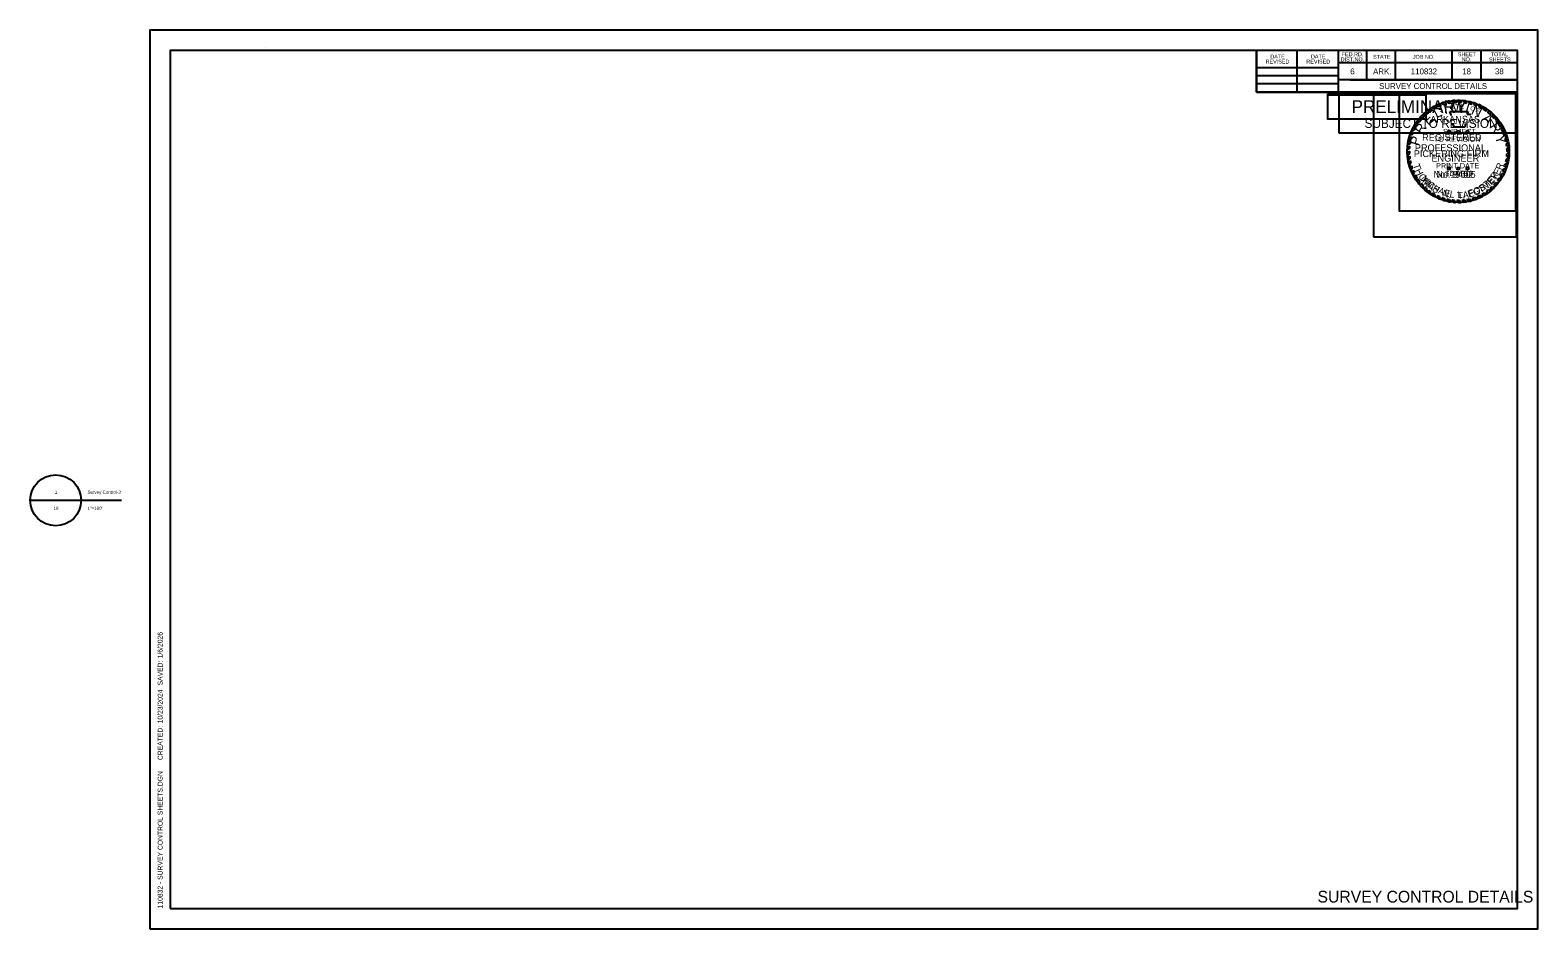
# Model space of a CAD drawing. Extents: x -0.12 to 1.42, y 0 to 0.92.
import ezdxf

# ---------------------------------------------------------------- set-up
doc = ezdxf.new("R2010")
doc.units = 0
for name, color, linetype in [('Default', 7, 'Continuous'), ('DSN_DRFT_Guideline-No-Plot', 7, 'Continuous'), ('SHET_Annotations', 7, 'Continuous'), ('SHET_Border-Lines', 7, 'Continuous'), ('SHET_Border-Text', 7, 'Continuous'), ('SHET_Stamp-Prelim', 7, 'Continuous'), ('SHET_Stamp-Seal', 7, 'Continuous'), ('STAMP_PE DIG SIG', 7, 'Continuous'), ('STAMP_PE_BACKGROUND', 7, 'Continuous'), ('STAMP_PE_FOSTER', 7, 'Continuous'), ('STAMP_PE_SEAL-INFO', 7, 'Continuous'), ('STAMP_PE_TAEGTMEYER', 7, 'Continuous'), ('STAMP_PRELIMINARY', 7, 'Continuous')]:
    doc.layers.add(name, color=color, linetype=linetype)

msp = doc.modelspace()

# ---------------------------------------------------------------- linework, layer by layer
at = {"layer": 'Default'}
for p, q in [((-0.1223, 0.4371), (-0.0702, 0.4371)), ((-0.096, 0.4371), (-0.0291, 0.4371))]:
    msp.add_line(p, q, dxfattribs=at)
msp.add_circle((-0.0962, 0.4371), 0.026, dxfattribs=at)
at = {"layer": 'DSN_DRFT_Guideline-No-Plot'}
msp.add_lwpolyline([(0, 0), (1.4167, 0), (1.4167, 0.9167), (0, 0.9167)], close=True, dxfattribs=at)
at = {"layer": 'SHET_Border-Lines'}
for p, q in [((0.1176, 0.8988), (0.1176, 0.8988)), ((0.1176, 0.8988), (0.1176, 0.8988)), ((1.1296, 0.8534), (1.1296, 0.8958)), ((1.1711, 0.8534), (1.1711, 0.8958)), ((1.2127, 0.8958), (1.2127, 0.8534)), ((1.2417, 0.8958), (1.2417, 0.866)), ((1.2712, 0.8958), (1.2712, 0.866)), ((1.3289, 0.8958), (1.3289, 0.866)), ((1.3584, 0.8958), (1.3584, 0.866)), ((1.1296, 0.8786), (1.2127, 0.8786)), ((1.3958, 0.8832), (1.2127, 0.8832)), ((1.3958, 0.8833), (1.3958, 0.8833)), ((1.1296, 0.8706), (1.2127, 0.8706)), ((1.1296, 0.8622), (1.2127, 0.8622)), ((1.3958, 0.866), (1.2127, 0.866)), ((1.2252, 0.866), (1.3958, 0.866)), ((1.3958, 0.8534), (1.1296, 0.8534))]:
    msp.add_line(p, q, dxfattribs=at)
for points in [[(0.0208, 0.0208), (1.3958, 0.0208), (1.3958, 0.8958), (0.0208, 0.8958)], [(1.1296, 0.8534), (1.3958, 0.8534), (1.3958, 0.8958), (1.1296, 0.8958)]]:
    msp.add_lwpolyline(points, close=True, dxfattribs=at)
at = {"layer": 'SHET_Stamp-Prelim'}
msp.add_lwpolyline([(1.2137, 0.8119), (1.3948, 0.8119), (1.3948, 0.8524), (1.2137, 0.8524)], close=True, dxfattribs=at)
at = {"layer": 'SHET_Stamp-Seal'}
msp.add_line((1.3219, 0.7895), (1.3219, 0.7895), dxfattribs=at)
msp.add_lwpolyline([(1.249, 0.7057), (1.3948, 0.7057), (1.3948, 0.8524), (1.249, 0.8524)], close=True, dxfattribs=at)
at = {"layer": 'STAMP_PE DIG SIG'}
msp.add_lwpolyline([(1.2022, 0.8508), (1.3022, 0.8508), (1.3022, 0.8258), (1.2022, 0.8258)], close=True, dxfattribs=at)
at = {"layer": 'STAMP_PE_BACKGROUND'}
for points in [[(1.2022, 0.8517), (1.3022, 0.8517), (1.3022, 0.8258), (1.2022, 0.8258)], [(1.3942, 0.8517), (1.275, 0.8517), (1.275, 0.7325), (1.3942, 0.7325)]]:
    msp.add_lwpolyline(points, close=True, dxfattribs=at)
at = {"layer": 'STAMP_PE_SEAL-INFO'}
for p, q in [((1.3002, 0.8313), (1.3028, 0.8306)), ((1.3021, 0.833), (1.3051, 0.8325)), ((1.3042, 0.8348), (1.3068, 0.8337)), ((1.3066, 0.8363), (1.309, 0.8352)), ((1.3087, 0.8377), (1.3112, 0.8365)), ((1.3112, 0.8391), (1.3138, 0.8378)), ((1.3137, 0.8403), (1.3158, 0.8387)), ((1.3165, 0.8415), (1.3181, 0.8397)), ((1.3184, 0.8422), (1.3206, 0.8405)), ((1.3217, 0.8432), (1.3233, 0.8413)), ((1.3239, 0.8438), (1.3259, 0.8418)), ((1.3266, 0.8443), (1.3283, 0.8422)), ((1.3269, 0.8337), (1.3456, 0.8337)), ((1.3276, 0.832), (1.3269, 0.8337)), ((1.3281, 0.8303), (1.3276, 0.832)), ((1.3295, 0.8447), (1.331, 0.8426)), ((1.3336, 0.8427), (1.3318, 0.8449)), ((1.3364, 0.8428), (1.3348, 0.845)), ((1.3389, 0.8426), (1.3375, 0.845)), ((1.3417, 0.8424), (1.3401, 0.8448)), ((1.3441, 0.842), (1.3427, 0.8445)), ((1.3456, 0.8337), (1.3443, 0.831)), ((1.3473, 0.8413), (1.3463, 0.8439)), ((1.3495, 0.8407), (1.3486, 0.8433)), ((1.352, 0.8399), (1.3512, 0.8426)), ((1.3544, 0.839), (1.3536, 0.8418)), ((1.357, 0.8379), (1.3564, 0.8406)), ((1.3594, 0.8366), (1.359, 0.8394)), ((1.3616, 0.8353), (1.3614, 0.8381)), ((1.364, 0.8337), (1.3639, 0.8366)), ((1.366, 0.8322), (1.3662, 0.8349)), ((1.3685, 0.8301), (1.3687, 0.8331)), ((1.3703, 0.8285), (1.3707, 0.8313)), ((1.2891, 0.8167), (1.2918, 0.8171)), ((1.2904, 0.8191), (1.2931, 0.8192)), ((1.2917, 0.8213), (1.2946, 0.8215)), ((1.293, 0.8232), (1.2959, 0.8232)), ((1.2946, 0.8253), (1.2977, 0.8254)), ((1.2965, 0.8276), (1.2994, 0.8274)), ((1.2983, 0.8295), (1.3014, 0.8293)), ((1.3282, 0.8297), (1.3281, 0.8303)), ((1.3293, 0.8201), (1.3291, 0.8213)), ((1.331, 0.8201), (1.3293, 0.8201)), ((1.331, 0.8177), (1.331, 0.8201)), ((1.3423, 0.8177), (1.331, 0.8177)), ((1.3424, 0.8196), (1.3423, 0.8177)), ((1.3429, 0.8213), (1.3424, 0.8196)), ((1.3443, 0.831), (1.3478, 0.831)), ((1.3478, 0.831), (1.347, 0.8297)), ((1.3723, 0.8264), (1.3727, 0.8294)), ((1.3738, 0.8247), (1.3746, 0.8273)), ((1.3756, 0.8223), (1.3764, 0.8251)), ((1.3769, 0.8206), (1.3779, 0.8232)), ((1.3786, 0.8178), (1.3796, 0.8205)), ((1.3797, 0.8157), (1.381, 0.8182)), ((1.381, 0.813), (1.3823, 0.8157)), ((1.2862, 0.8008), (1.2838, 0.7996)), ((1.2867, 0.8034), (1.2841, 0.802)), ((1.2847, 0.8048), (1.2873, 0.8059)), ((1.2853, 0.8071), (1.2879, 0.808)), ((1.2862, 0.8099), (1.2889, 0.8106)), ((1.287, 0.8121), (1.2898, 0.8129)), ((1.288, 0.8145), (1.2908, 0.8151)), ((1.3252, 0.8129), (1.3241, 0.8137)), ((1.3241, 0.8137), (1.3255, 0.8137)), ((1.3248, 0.8116), (1.3252, 0.8129)), ((1.3259, 0.8124), (1.3248, 0.8116)), ((1.3255, 0.8137), (1.3259, 0.815)), ((1.3259, 0.815), (1.3264, 0.8137)), ((1.327, 0.8116), (1.3259, 0.8124)), ((1.3264, 0.8137), (1.3277, 0.8137)), ((1.3277, 0.8137), (1.3266, 0.8129)), ((1.3266, 0.8129), (1.327, 0.8116)), ((1.3347, 0.8129), (1.3336, 0.8137)), ((1.3336, 0.8137), (1.335, 0.8137)), ((1.3343, 0.8116), (1.3347, 0.8129)), ((1.3354, 0.8124), (1.3343, 0.8116)), ((1.335, 0.8137), (1.3354, 0.815)), ((1.3354, 0.815), (1.3358, 0.8137)), ((1.3365, 0.8116), (1.3354, 0.8124)), ((1.3358, 0.8137), (1.3372, 0.8137)), ((1.3372, 0.8137), (1.3361, 0.8129)), ((1.3361, 0.8129), (1.3365, 0.8116)), ((1.3442, 0.8129), (1.3431, 0.8137)), ((1.3431, 0.8137), (1.3445, 0.8137)), ((1.3438, 0.8116), (1.3442, 0.8129)), ((1.3449, 0.8124), (1.3438, 0.8116)), ((1.3445, 0.8137), (1.3449, 0.815)), ((1.3449, 0.815), (1.3453, 0.8137)), ((1.346, 0.8116), (1.3449, 0.8124)), ((1.3453, 0.8137), (1.3467, 0.8137)), ((1.3467, 0.8137), (1.3456, 0.8129)), ((1.3456, 0.8129), (1.346, 0.8116)), ((1.3818, 0.8112), (1.3832, 0.8136)), ((1.3829, 0.8081), (1.3844, 0.8107)), ((1.3835, 0.8061), (1.3851, 0.8086)), ((1.3842, 0.8029), (1.386, 0.8054)), ((1.3846, 0.8008), (1.3866, 0.8028)), ((1.2857, 0.796), (1.2834, 0.7946)), ((1.2856, 0.7933), (1.2834, 0.7914)), ((1.2859, 0.7984), (1.2835, 0.7968)), ((1.2857, 0.791), (1.2835, 0.7892)), ((1.2858, 0.7882), (1.2838, 0.7862)), ((1.2861, 0.7858), (1.2842, 0.7837)), ((1.3846, 0.7855), (1.3871, 0.7867)), ((1.3849, 0.7876), (1.3874, 0.7891)), ((1.385, 0.798), (1.387, 0.7998)), ((1.3851, 0.7956), (1.3873, 0.7973)), ((1.3852, 0.7927), (1.3875, 0.7945)), ((1.3852, 0.7905), (1.3875, 0.792)), ((1.2866, 0.7833), (1.2847, 0.7812)), ((1.2871, 0.7809), (1.2854, 0.7786)), ((1.2878, 0.7784), (1.2861, 0.7761)), ((1.2886, 0.7761), (1.287, 0.7738)), ((1.2895, 0.7737), (1.288, 0.7713)), ((1.2905, 0.7715), (1.2892, 0.769)), ((1.3252, 0.7754), (1.3241, 0.7763)), ((1.3241, 0.7763), (1.3255, 0.7763)), ((1.3248, 0.7741), (1.3252, 0.7754)), ((1.3259, 0.7749), (1.3248, 0.7741)), ((1.3255, 0.7763), (1.3259, 0.7776)), ((1.3259, 0.7776), (1.3264, 0.7763)), ((1.327, 0.7741), (1.3259, 0.7749)), ((1.3264, 0.7763), (1.3277, 0.7763)), ((1.3277, 0.7763), (1.3266, 0.7754)), ((1.3266, 0.7754), (1.327, 0.7741)), ((1.3347, 0.7754), (1.3336, 0.7763)), ((1.3336, 0.7763), (1.335, 0.7763)), ((1.3343, 0.7741), (1.3347, 0.7754)), ((1.3354, 0.7749), (1.3343, 0.7741)), ((1.335, 0.7763), (1.3354, 0.7776)), ((1.3354, 0.7776), (1.3358, 0.7763)), ((1.3365, 0.7741), (1.3354, 0.7749)), ((1.3358, 0.7763), (1.3372, 0.7763)), ((1.3372, 0.7763), (1.3361, 0.7754)), ((1.3361, 0.7754), (1.3365, 0.7741)), ((1.3442, 0.7754), (1.3431, 0.7763)), ((1.3431, 0.7763), (1.3445, 0.7763)), ((1.3438, 0.7741), (1.3442, 0.7754)), ((1.3449, 0.7749), (1.3438, 0.7741)), ((1.3445, 0.7763), (1.3449, 0.7776)), ((1.3449, 0.7776), (1.3453, 0.7763)), ((1.346, 0.7741), (1.3449, 0.7749)), ((1.3453, 0.7763), (1.3467, 0.7763)), ((1.3467, 0.7763), (1.3456, 0.7754)), ((1.3456, 0.7754), (1.346, 0.7741)), ((1.3799, 0.7705), (1.3826, 0.7709)), ((1.3808, 0.7724), (1.3835, 0.7729)), ((1.382, 0.7753), (1.3847, 0.776)), ((1.3827, 0.7774), (1.3855, 0.7785)), ((1.3835, 0.7802), (1.3862, 0.7813)), ((1.3841, 0.7827), (1.3867, 0.7838)), ((1.2918, 0.769), (1.2907, 0.7662)), ((1.2931, 0.7667), (1.2921, 0.7641)), ((1.2942, 0.765), (1.2936, 0.7619)), ((1.2958, 0.7628), (1.2952, 0.7598)), ((1.2975, 0.7607), (1.297, 0.7578)), ((1.2992, 0.7588), (1.2988, 0.7559)), ((1.301, 0.757), (1.3008, 0.754)), ((1.3029, 0.7552), (1.3029, 0.7523)), ((1.3679, 0.7553), (1.3706, 0.7545)), ((1.3702, 0.7573), (1.3727, 0.7566)), ((1.3716, 0.7588), (1.3743, 0.7583)), ((1.3738, 0.7612), (1.3763, 0.7608)), ((1.3755, 0.7634), (1.3783, 0.7634)), ((1.3774, 0.7662), (1.3801, 0.7661)), ((1.3783, 0.7677), (1.3811, 0.768)), ((1.3049, 0.7536), (1.305, 0.7507)), ((1.3068, 0.7522), (1.307, 0.7493)), ((1.3092, 0.7506), (1.3095, 0.7478)), ((1.3111, 0.7495), (1.3117, 0.7466)), ((1.3138, 0.7481), (1.3147, 0.7452)), ((1.3159, 0.7471), (1.3169, 0.7443)), ((1.3187, 0.7461), (1.3198, 0.7433)), ((1.321, 0.7453), (1.3222, 0.7426)), ((1.3238, 0.7445), (1.325, 0.7419)), ((1.326, 0.7441), (1.3274, 0.7415)), ((1.3288, 0.7436), (1.3302, 0.7411)), ((1.3313, 0.7433), (1.3328, 0.7409)), ((1.334, 0.7432), (1.3356, 0.7409)), ((1.3365, 0.7432), (1.3384, 0.741)), ((1.3394, 0.7433), (1.3412, 0.7412)), ((1.3419, 0.7436), (1.344, 0.7416)), ((1.3444, 0.744), (1.3465, 0.7421)), ((1.3471, 0.7446), (1.3492, 0.7427)), ((1.3497, 0.7453), (1.352, 0.7436)), ((1.3524, 0.7462), (1.3549, 0.7447)), ((1.3548, 0.7471), (1.3571, 0.7456)), ((1.3573, 0.7483), (1.36, 0.7471)), ((1.3596, 0.7494), (1.3619, 0.7481)), ((1.3619, 0.7508), (1.3644, 0.7497)), ((1.3639, 0.7521), (1.3663, 0.751)), ((1.3664, 0.754), (1.369, 0.7532))]:
    msp.add_line(p, q, dxfattribs=at)
for radius, start, end in [(0.0521, 129.7326, 132.5376), (0.0498, 127.5297, 130.9683), (0.0521, 123.6199, 126.5906), (0.0498, 121.9746, 125.11), (0.0521, 117.6544, 120.8099), (0.0498, 115.6869, 119.1583), (0.0521, 111.3124, 114.7026), (0.0498, 110.3086, 113.1659), (0.0521, 105.2339, 109.0352), (0.0498, 104.0352, 107.3615), (0.0521, 99.7525, 102.7765), (0.0498, 98.258, 101.0329), (0.0521, 93.9381, 96.5517), (0.0498, 92.1102, 95.0367), (0.0521, 87.7298, 90.6707), (0.0498, 85.9628, 88.9097), (0.0521, 81.9732, 84.8236), (0.0498, 79.9264, 82.696), (0.0521, 75.3125, 77.9426), (0.0498, 73.5575, 76.2314), (0.0521, 69.6061, 72.3058), (0.0498, 67.6248, 70.504), (0.0521, 63.1329, 66.2704), (0.0498, 61.1558, 64.3784), (0.0521, 56.9003, 60.0942), (0.0498, 54.9238, 58.2702), (0.0498, 48.3016, 52.0395), (0.0521, 50.3492, 53.7159), (0.0521, 44.3405, 47.3929), (0.0521, 152.864, 155.5189), (0.0521, 147.0072, 149.899), (0.0498, 151.0315, 153.573), (0.0521, 141.6056, 144.4486), (0.0498, 145.0197, 148.2104), (0.0498, 139.301, 142.5873), (0.0521, 135.4021, 138.3031), (0.0498, 133.1331, 136.2562), (0.0498, 42.2212, 45.5512), (0.0498, 36.135, 39.5311), (0.0521, 38.1247, 41.2316), (0.0498, 29.9032, 33.6645), (0.0521, 31.9614, 35.4294), (0.0498, 23.7732, 27.2211), (0.0521, 25.9391, 29.0125), (0.0521, 170.0003, 172.6878), (0.0521, 164.3068, 166.894), (0.0521, 158.4077, 161.0701), (0.0498, 167.9048, 170.9039), (0.0498, 162.4331, 165.0013), (0.0498, 156.3402, 159.2319), (0.0498, 17.6802, 21.4251), (0.0521, 19.9538, 23.3141), (0.0498, 11.5444, 15.2364), (0.0498, 5.7599, 9.0606), (0.0521, 13.8421, 17.4447), (0.0521, 7.5852, 10.8621), (0.0521, 175.7409, 178.2066), (0.0521, 181.7251, 184.1626), (0.0521, 187.4204, 190.1927), (0.0498, 179.6454, 182.2633), (0.0498, 173.73, 176.4734), (0.0498, 185.4539, 188.234), (0.0498, 348.0778, 351.3435), (0.0498, 353.8632, 357.1274), (0.0498, 359.7329, 3.0639), (0.0521, 349.8305, 353.0885), (0.0521, 1.7215, 4.7268), (0.0521, 355.7156, 358.9569), (0.0521, 193.0369, 195.9973), (0.0521, 198.8967, 201.6281), (0.0498, 191.2274, 193.9858), (0.0498, 196.9675, 199.8353), (0.0521, 204.5479, 207.4328), (0.0498, 202.7761, 205.4791), (0.0498, 329.5549, 333.2076), (0.0498, 335.6038, 339.1858), (0.0521, 331.4037, 334.9332), (0.0498, 341.777, 345.0925), (0.0521, 337.3837, 340.9933), (0.0521, 343.8925, 347.035), (0.0521, 210.8636, 213.6571), (0.0498, 208.7883, 211.7934), (0.0521, 216.6115, 219.491), (0.0498, 214.1838, 217.2747), (0.0521, 222.48, 225.3801), (0.0498, 220.3909, 223.3056), (0.0498, 226.2494, 229.2407), (0.0498, 310.7744, 314.3161), (0.0521, 312.4518, 315.6633), (0.0498, 316.6531, 320.3711), (0.0521, 318.2846, 321.8043), (0.0498, 323.5851, 327.4407), (0.0521, 325.4405, 328.9872), (0.0521, 228.3665, 231.348), (0.0498, 232.229, 234.9336), (0.0521, 234.295, 236.9452), (0.0498, 238.2223, 240.8353), (0.0521, 240.1977, 242.8613), (0.0498, 244.3204, 246.9486), (0.0521, 246.576, 249.1558), (0.0498, 250.3491, 253.1216), (0.0521, 252.5967, 255.3252), (0.0498, 256.505, 259.1192), (0.0521, 258.4433, 261.1398), (0.0498, 262.3783, 265.2012), (0.0521, 264.1978, 267.1009), (0.0498, 268.3215, 271.277), (0.0521, 270.2548, 273.3361), (0.0498, 274.6157, 277.4486), (0.0521, 276.4239, 279.4357), (0.0498, 280.3459, 283.5814), (0.0521, 282.3199, 285.3702), (0.0498, 286.6423, 289.9783), (0.0521, 288.5709, 291.9733), (0.0498, 292.8745, 296.1185), (0.0521, 294.6481, 298.2166), (0.0498, 299.0768, 302.1724), (0.0521, 300.621, 303.8703), (0.0498, 304.823, 308.5143), (0.0521, 306.3721, 310.208)]:
    msp.add_arc((1.3354, 0.793), radius, start, end, dxfattribs=at)
at = {"layer": 'STAMP_PRELIMINARY'}
msp.add_circle((1.3354, 0.793), 0.0521, dxfattribs=at)

# ---------------------------------------------------------------- texts
at = {"layer": 'Default'}
for s, height, p in [('1', 0.00328, (-0.0971, 0.4437)), ('Survey Control-3', 0.003281, (-0.0637, 0.4437)), ('18', 0.00328, (-0.0984, 0.4273)), ('1"=100\'', 0.00328, (-0.0637, 0.4273))]:
    msp.add_text(s, height=height, dxfattribs=at).set_placement(p)
at = {"layer": 'SHET_Annotations'}
for s, height, p in [('6', 0.006, (1.2252, 0.8716)), ('ARK.', 0.006, (1.2485, 0.8716)), ('110832', 0.006, (1.287, 0.8716)), ('18', 0.006, (1.3395, 0.8716)), ('38', 0.006, (1.3729, 0.8717)), ('SURVEY CONTROL DETAILS', 0.006, (1.2547, 0.8567)), ('SURVEY CONTROL DETAILS', 0.012, (1.1918, 0.0268))]:
    msp.add_text(s, height=height, dxfattribs=at).set_placement(p)
at = {"layer": 'SHET_Border-Text'}
for s, p in [('FED.RD.', (1.2165, 0.8901)), ('SHEET', (1.335, 0.8901)), ('TOTAL', (1.3686, 0.8901)), ('REVISED', (1.1388, 0.8826)), ('DATE', (1.1436, 0.8878)), ('REVISED', (1.1804, 0.8826)), ('DATE', (1.1851, 0.8878)), ('DIST.NO.', (1.2154, 0.8849)), ('STATE', (1.2485, 0.8875)), ('JOB NO.', (1.2891, 0.8875)), ('NO.', (1.339, 0.8849)), ('SHEETS', (1.3668, 0.8849))]:
    msp.add_text(s, height=0.004, dxfattribs=at).set_placement(p)
for s, p in [('1/6/2026', (0.0129, 0.2759)), ('  SAVED: ', (0.0129, 0.2444)), ('10/23/2024', (0.0129, 0.2095)), ('     CREATED: ', (0.0129, 0.1625)), ('110832 - SURVEY CONTROL SHEETS.DGN', (0.0129, 0.0208))]:
    msp.add_text(s, height=0.005, rotation=90, dxfattribs=at).set_placement(p)
at = {"layer": 'SHET_Stamp-Prelim'}
for s, height, p in [('PRELIMINARY', 0.013, (1.2266, 0.8322)), ('SUBJECT TO REVISION', 0.009, (1.2398, 0.817))]:
    msp.add_text(s, height=height, dxfattribs=at).set_placement(p)
at = {"layer": 'STAMP_PE_FOSTER'}
msp.add_text('No. 9402', height=0.00698, dxfattribs=at).set_placement((1.313, 0.7661))
for s, rotation, p in [('R', 54.5031, (1.373, 0.764)), ('M', 308.339, (1.297, 0.7652)), ('I', 314.1842, (1.3014, 0.7599)), ('C', 319.8733, (1.3034, 0.7579)), ('H', 327.7235, (1.3086, 0.7538)), ('A', 335.7276, (1.3141, 0.7506)), ('E', 343.5779, (1.3204, 0.748)), ('F', 15.8691, (1.3468, 0.7469)), ('O', 23.719, (1.3526, 0.7487)), ('S', 31.7234, (1.3588, 0.7517)), ('T', 39.4194, (1.3641, 0.7552)), ('E', 46.9613, (1.3689, 0.7594)), ('L', 350.8115, (1.3263, 0.7464)), ('L', 1.2666, (1.3349, 0.7455)), ('.', 6.8035, (1.3408, 0.7459))]:
    msp.add_text(s, height=0.0067, rotation=rotation, dxfattribs=at).set_placement(p)
at = {"layer": 'STAMP_PE_SEAL-INFO'}
for s, rotation, p in [('S', 23.5541, (1.3164, 0.8327)), ('T', 16.311, (1.3216, 0.8347)), ('A', 9.0679, (1.3269, 0.8361)), ('T', 1.8248, (1.3325, 0.8369)), ('E', 355.2002, (1.3375, 0.8369)), ('O', 342.2506, (1.3472, 0.8354)), ('F', 335.0075, (1.3526, 0.8335))]:
    msp.add_text(s, height=0.00436, rotation=rotation, dxfattribs=at).set_placement(p)
for s, height, p in [('ARKANSAS', 0.00698, (1.3069, 0.8223)), ('PROFESSIONAL', 0.006983, (1.2911, 0.7932)), ('REGISTERED', 0.00698, (1.2986, 0.8038)), ('ENGINEER', 0.00698, (1.3081, 0.7826))]:
    msp.add_text(s, height=height, dxfattribs=at).set_placement(p)
at = {"layer": 'STAMP_PE_TAEGTMEYER'}
for s, rotation, p in [('T', 289.646, (1.289, 0.7791)), ('H', 296.7339, (1.291, 0.7736)), ('O', 303.7708, (1.2943, 0.7674)), ('Y', 53.9986, (1.3733, 0.7628)), ('E', 63.0984, (1.377, 0.768)), ('R', 69.57, (1.3798, 0.7735)), ('M', 314.2033, (1.298, 0.7621)), ('A', 321.0594, (1.3034, 0.7567)), ('S', 327.8239, (1.308, 0.7531)), ('G', 23.3052, (1.3522, 0.7475)), ('T', 31.466, (1.3583, 0.7503)), ('M', 39.3, (1.3633, 0.7533)), ('E', 46.8094, (1.3692, 0.7582)), ('N', 344.2727, (1.3186, 0.7474)), ('.', 350.6464, (1.3254, 0.7456)), ('T', 3.0061, (1.3347, 0.7445)), ('A', 8.9826, (1.3405, 0.7448)), ('E', 17.6836, (1.3463, 0.7457))]:
    msp.add_text(s, height=0.00698, rotation=rotation, dxfattribs=at).set_placement(p)
msp.add_text('No. 19605', height=0.00698, dxfattribs=at).set_placement((1.3101, 0.7661))
at = {"layer": 'STAMP_PRELIMINARY'}
for s, rotation, p in [('E', 42.3578, (1.3048, 0.8192)), ('L', 25.513, (1.3131, 0.8266)), ('I', 12.5248, (1.3217, 0.8309)), ('M', 3.1074, (1.3278, 0.8326)), ('I', 342.3164, (1.3416, 0.833)), ('N', 333.9382, (1.3478, 0.8315)), ('R', 56.2292, (1.2984, 0.8095)), ('A', 315.6579, (1.3591, 0.8257)), ('R', 301.3831, (1.3668, 0.8184)), ('P', 73.913, (1.2953, 0.7982)), ('Y', 283.2593, (1.3729, 0.8084))]:
    msp.add_text(s, height=0.0101, rotation=rotation, dxfattribs=at).set_placement(p)
for s, height, p in [('SUBJECT', 0.00536, (1.3198, 0.8106)), ('TO REVISION', 0.005363, (1.3105, 0.8028)), ('PICKERING FIRM', 0.006983, (1.29, 0.7872)), ('PRINT DATE', 0.00536, (1.3128, 0.7757)), ('$DATE$', 0.00536, (1.3222, 0.768))]:
    msp.add_text(s, height=height, dxfattribs=at).set_placement(p)

doc.saveas('drawing.dxf')
